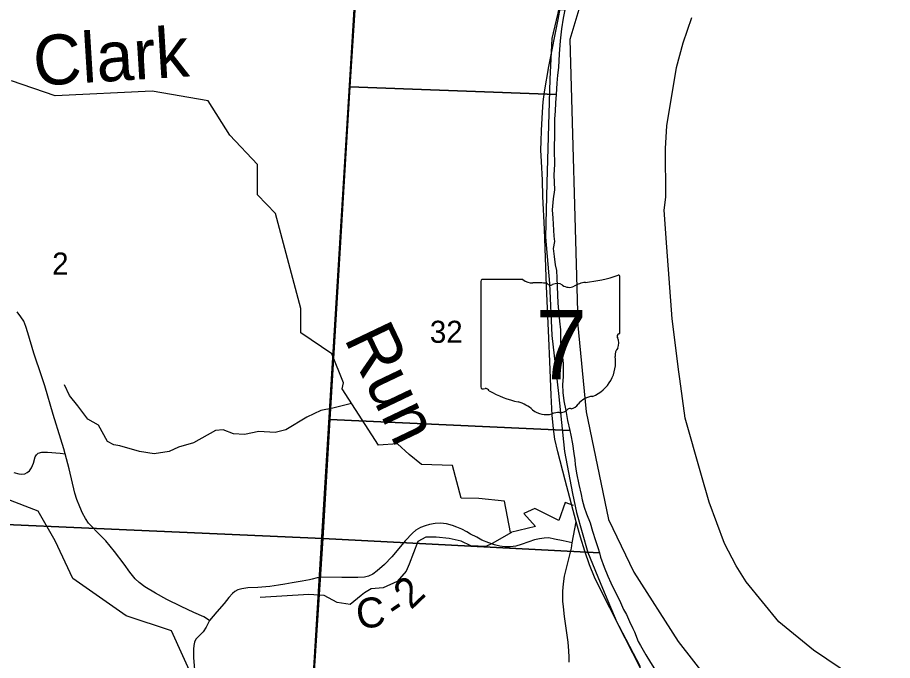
# Model space of a CAD drawing. Extents: x 1878108 to 2183446, y 146837 to 508383.
# Drawn here: x 2042273 to 2051033, y 280407 to 286848 of the extents above; entities that cross this region are included whole.
import ezdxf

# ---------------------------------------------------------------- set-up
doc = ezdxf.new("R2010")
doc.units = 0
for name, color, linetype in [('GM_X_County', 7, 'Continuous'), ('GM_X_County_Road', 7, 'Continuous'), ('GM_X_County_Road_Text', 7, 'Continuous'), ('GM_X_Major_River', 7, 'Continuous'), ('GM_X_Minor_River', 7, 'Continuous'), ('GM_X_Minor_River_Text', 7, 'Continuous'), ('GM_X_Section', 7, 'Continuous'), ('GM_X_Section_Text', 7, 'Continuous'), ('GM_X_State_Location', 7, 'Continuous'), ('GM_X_State_Route', 7, 'Continuous'), ('GM_X_State_Shield', 7, 'Continuous'), ('GM_X_Township', 7, 'Continuous'), ('GM_X_Township_Road', 7, 'Continuous')]:
    doc.layers.add(name, color=color, linetype=linetype)

msp = doc.modelspace()

# ---------------------------------------------------------------- linework, layer by layer
at = {"layer": 'GM_X_County'}
msp.add_lwpolyline([(2047973.9, 287198), (2047804.2, 286626.9), (2047880.1, 283903.6), (2047878.1, 283797.4), (2047965.9, 282897.6), (2048191.4, 281819.5), (2048444.9, 281292.4), (2048888.4, 280598.3), (2049170.8, 280234.4)], dxfattribs=at)
at = {"layer": 'GM_X_County_Road'}
for points in [[(2045221.5, 281222.3), (2045197.8, 281216.5), (2045124.2, 281200.7), (2045022.2, 281183.9), (2044948.6, 281172.3), (2044885.5, 281161.8), (2044800.3, 281149.2), (2044678.3, 281138.6), (2044580.4, 281134.4), (2044517.3, 281126), (2044479.5, 281115.5), (2044450, 281099.7), (2044424.8, 281078.7), (2044390.1, 281039.8), (2044341.7, 280978.8), (2044269.1, 280894.6), (2044230.2, 280850.5), (2044195.5, 280807.3), (2044136.6, 280845.2), (2044037.7, 280889.4), (2043910.5, 280949.3), (2043767.4, 281019.1), (2043654.9, 281081.8), (2043548.2, 281145.5), (2043489.8, 281188.1), (2043449.8, 281227), (2043397.2, 281293.2), (2043339.4, 281372.1), (2043244.7, 281499.4), (2043157.4, 281607.7), (2043064.9, 281700.3), (2043025.9, 281738.1), (2042982.2, 281784), (2042952.3, 281829.6), (2042923.9, 281882.2), (2042896.6, 281945.3), (2042868.2, 282019), (2042846.1, 282085.2), (2042790.4, 282327.1), (2042751.4, 282478.6), (2042736.7, 282529.1), (2042706.2, 282625.8), (2042628.4, 282873), (2042546.3, 283160.1), (2042516.9, 283247.4), (2042435.9, 283486.2), (2042374.9, 283689.2), (2042357, 283754.4), (2042334.9, 283804.9), (2042307.6, 283850.1), (2042269.7, 283898.5)], [(2047825.9, 281585.2), (2047734.7, 281606.7), (2047649, 281624), (2047591.6, 281635.1), (2047546.4, 281634), (2047498, 281626.7), (2047449.6, 281615.1), (2047391.8, 281595.1), (2047317.1, 281568.8), (2047262.4, 281553), (2047208.8, 281545.7), (2047152, 281546.7), (2047100.5, 281552), (2047050, 281566.7), (2046991.1, 281584.6), (2046922.7, 281614), (2046871.2, 281642.4), (2046808.7, 281672.4), (2046772.3, 281695), (2046721.8, 281721.3), (2046672.4, 281742.3), (2046629.3, 281761.3), (2046567.2, 281776), (2046508.3, 281783.4), (2046454.7, 281780.2), (2046398.9, 281768.6), (2046355.8, 281757.1), (2046307.4, 281738.1), (2046262.2, 281714), (2046226.5, 281681.3), (2046154.9, 281606.7), (2046073.9, 281509.9), (2046019.3, 281446.8), (2045945.6, 281370), (2045875.2, 281305.9), (2045831, 281271.2), (2045786.8, 281253.3), (2045745.8, 281242.8), (2045681.6, 281239.6), (2045518.6, 281239.6), (2045314.6, 281240.7), (2045294, 281238), (2045274.6, 281235.4), (2045221.5, 281222.3)], [(2044195.5, 280807.3), (2044162.8, 280740.2), (2044131.3, 280693.4), (2044059, 280622.6), (2044043.4, 280590.2), (2044037.6, 280558.7), (2044034.8, 280519.5), (2044034.8, 280433.5), (2044054.8, 280196.6)]]:
    msp.add_lwpolyline(points, dxfattribs=at)
at = {"layer": 'GM_X_Major_River'}
for points in [[(2047757, 287204.5), (2047623.5, 286636.6), (2047601.2, 286229.6), (2047573.4, 285191.2), (2047559.6, 284647.9), (2047599.4, 284183), (2047623.5, 283664), (2047687.7, 283082.9), (2047749.9, 282499.9), (2047829.4, 282081.3), (2047868.1, 281889), (2047981.5, 281490.6), (2048130.6, 281130.4), (2048273.7, 280790.2), (2048511.1, 280326.1)], [(2048763.6, 285047.7), (2048761.7, 285534.8), (2048774.7, 285763.3), (2048872.2, 286349), (2048939.1, 286593.9), (2049023.9, 286848.8)], [(2051033.4, 279977.5), (2050240.9, 280509.5), (2049894.4, 280794.7), (2049567.5, 281194.3), (2049469, 281354.3), (2049352.4, 281580.3), (2049199, 281992.6), (2049116, 282284.9), (2048956.1, 282835.5), (2048902.7, 283228.2), (2048894.4, 283298.3), (2048828.4, 283829.2), (2048773.6, 284548.6), (2048748.2, 284917.3), (2048763.6, 285047.7)]]:
    msp.add_lwpolyline(points, dxfattribs=at)
at = {"layer": 'GM_X_Minor_River'}
for points in [[(2047840.4, 281959.9), (2047756.9, 281991.4), (2047693.1, 281810.5), (2047451, 281930.6), (2047341.4, 281879.5), (2047459.4, 281750.3), (2047209.7, 281687.9), (2047149.4, 282004), (2046890.5, 282029.8), (2046714.1, 282032.2), (2046629.5, 282362.1), (2046316.8, 282369.4), (2046193.1, 282472.5), (2046077.5, 282577.7), (2045887.2, 282566), (2045523.1, 283127.9), (2045536.3, 283188.1), (2045420.2, 283479.7), (2045110.8, 283689.4), (2045109.6, 283933.9), (2044854.5, 284885.5), (2044675.7, 285072.3), (2044675.7, 285375), (2044397.2, 285671.1), (2044180.2, 286013.9), (2043621.7, 286109.1), (2042650.2, 286062.3), (2042213.3, 286212.8)], [(2045616.7, 282983.3), (2045431.1, 282934.2), (2045311, 282912), (2045168.9, 282845.6), (2044960.7, 282718.9), (2044852.6, 282690.6), (2044690.5, 282702.5), (2044546.4, 282670.3), (2044434.3, 282678.2), (2044330.2, 282718.2), (2044254.1, 282712.1), (2044033.9, 282589.4), (2043885.8, 282545.1), (2043789.7, 282500.8), (2043641.6, 282478.6), (2043493.5, 282500.5), (2043297.4, 282558.5), (2043237.3, 282568.5), (2043173.3, 282600.6), (2043083.3, 282763.1), (2042977.2, 282825.2), (2042875.2, 282957.6), (2042793.2, 283061.9), (2042743.2, 283168.3)], [(2044058.6, 280166.7), (2043815, 280705.6), (2043360, 280855.9), (2042826, 281229.9), (2042650.6, 281607.1), (2042478.4, 281902.2), (2041835.7, 282151)], [(2047219, 281690.2), (2047025.9, 281580.7), (2046961.8, 281550.5), (2046811.7, 281556.4), (2046715.6, 281602.5), (2046595.5, 281628.4), (2046465.4, 281644.4), (2046359.4, 281642.2), (2046281.3, 281600), (2046195.1, 281371.1), (2046163.1, 281300.8), (2046075, 281200.3), (2045934.9, 281135.9), (2045812.8, 281123.7), (2045746.7, 281085.5), (2045712.7, 281057.4), (2045602.5, 280966.9), (2045472.4, 280988.9), (2045342.4, 281057), (2045188.3, 281066.9), (2044703.9, 281038.3)]]:
    msp.add_lwpolyline(points, dxfattribs=at)
at = {"layer": 'GM_X_Section'}
for points in [[(2040106.5, 287265.7), (2045656.8, 287027), (2045601, 286154.5), (2045400.1, 282821.2), (2045329.4, 281630.4), (2039736.5, 281877.8)], [(2047752, 286926.7), (2047736, 286840.1), (2047718.4, 286734), (2047704.8, 286616), (2047695.2, 286483.9), (2047687.7, 286347.8), (2047678, 286269.8), (2047672.2, 286191.7), (2047666.9, 286077.2), (2045601, 286154.5), (2045656.8, 287027)], [(2045601, 286154.5), (2047666.9, 286077.2), (2047658.9, 285993.6), (2047657.2, 285909.6), (2047649.5, 285831.6), (2047648, 285693.5), (2047646.6, 285523.5), (2047649.1, 285375.5), (2047641.4, 285273.4), (2047649.9, 285123.4), (2047636.2, 285031.3), (2047626.6, 284923.2), (2047630.9, 284837.2), (2047641.5, 284657.2), (2047649.7, 284605.3), (2047636, 284535.2), (2047644.3, 284453.2), (2047656.6, 284369.2), (2047670.8, 284313.2), (2047671, 284241.2), (2047679.6, 284071.2), (2047683.9, 283985.2), (2047698.5, 283807.2), (2047710.8, 283719.2), (2047709.3, 283593.2), (2047725.7, 283471.2), (2047736, 283383.2), (2047736.4, 283249.2), (2047728.7, 283173.2), (2047733, 283093.1), (2047743.3, 283007.2), (2047761.6, 282911.2), (2047780, 282811.2), (2047801.9, 282712.8), (2045400.1, 282821.2)], [(2047801.9, 282712.8), (2047812.5, 282665.3), (2047828.8, 282579.3), (2047843.1, 282481.4), (2047853.4, 282417.4), (2047855.5, 282369.4), (2047867.9, 282283.4), (2047892.2, 282169.4), (2047916.6, 282069.5), (2047924.8, 282015.5), (2047947, 281943.6), (2047969.3, 281877.7), (2048007.6, 281785.8), (2048029.9, 281701.8), (2048060.2, 281607.9), (2048084.5, 281538), (2048098.3, 281484.7), (2045329.4, 281630.4), (2045400.1, 282821.2)], [(2045329.4, 281630.4), (2045240.9, 280250.1), (2044999.7, 276331.9), (2039465.5, 276603.9), (2039401.5, 276605.8), (2039736.5, 281877.8)], [(2048098.3, 281484.7), (2048108.8, 281444), (2048147.2, 281342.1), (2048183.5, 281252.2), (2048213.8, 281186.3), (2048233.9, 281142.4), (2048300.4, 281010.6), (2048340.7, 280918.7), (2048368.9, 280868.8), (2048401.1, 280796.9), (2048433.4, 280729), (2048451.5, 280695), (2048487.8, 280597.1), (2048510, 280557.2), (2048564.3, 280465.3), (2048610.6, 280387.5), (2048650.8, 280323.6), (2048695, 280267.7), (2048763.3, 280200), (2048873.7, 280088.3), (2048907.9, 280050.4), (2048930.5, 280024.5), (2045240.9, 280250.1), (2045329.4, 281630.4)]]:
    msp.add_lwpolyline(points, close=True, dxfattribs=at)
at = {"layer": 'GM_X_State_Route'}
for points in [[(2047865.5, 281796.9), (2047865.5, 281796.9), (2047755.7, 282214.1), (2047683.2, 282496.9), (2047654, 282623.1), (2047637.6, 282727.1), (2047627.1, 282863.8), (2047615.4, 283066), (2047602.6, 283403.8), (2047592.7, 283637.4), (2047569.8, 284158.7), (2047547.6, 284726.7), (2047532.4, 285055), (2047527.8, 285217.5), (2047518.4, 285405.6), (2047513.7, 285519), (2047514.9, 285609), (2047517.7, 285714.8), (2047527.8, 285900), (2047537.1, 286005.1), (2047547.6, 286104.5), (2047590.9, 286356.9), (2047684.4, 286826.7), (2047729.9, 287070.9)], [(2047839.1, 281655.8), (2047865.5, 281796.9)], [(2048510.9, 280344.4), (2048296.4, 280751.7), (2048112.3, 281112.3), (2048051.3, 281242.8), (2048000.8, 281366.9), (2047952.4, 281501.5), (2047908.2, 281641.4), (2047865.5, 281796.9)], [(2047796.7, 280390.8), (2047796.7, 280442.4), (2047793.6, 280504.4), (2047785.2, 280591.7), (2047773.6, 280684.3), (2047750.5, 280847.3), (2047738.9, 280944.1), (2047733.6, 281001.9), (2047732.6, 281052.4), (2047732.6, 281102.9), (2047737.8, 281176.5), (2047750.5, 281251.2), (2047769.4, 281333.2), (2047817.8, 281533), (2047825.9, 281585.2), (2047839.1, 281655.8)]]:
    msp.add_lwpolyline(points, dxfattribs=at)
at = {"layer": 'GM_X_State_Shield'}
for p, q in [((2046912.2, 284204.8), (2046912.2, 283148.2)), ((2047333.6, 284223), (2046925.9, 284223)), ((2048304.3, 283696.4), (2048304.3, 284249.2)), ((2048304.2, 283696.6), (2048304.3, 283696.4))]:
    msp.add_line(p, q, dxfattribs=at)
for centre, radius, start, end in [((2046928.1, 284207.1), 16.1, 98.1301, 188.1301), ((2047430.7, 284345.7), 156.4, 231.61951, 271.11188), ((2047808.4, 285663.6), 1476.4, 275.84447, 288.90645), ((2048288.9, 284251.5), 15.5, 351.86209, 97.738), ((2047482.5, 283629.8), 561.6, 80.48669, 94.98827), ((2047610, 284212.5), 45.1, 219.79206, 297.10237), ((2047676.3, 284090.4), 93.8, 54.46668, 119.14113), ((2047797.4, 284257.9), 112.9, 233.85621, 294.82819), ((2047996.7, 283900.3), 297, 97.34618, 120.76885), ((2048300.7, 283655.9), 24, 107.94398, 210.33697), ((2048287.8, 283694.3), 16.6, 289.60381, 7.73413), ((2048148.2, 283586), 144, 340.03296, 23.64957), ((2048359.9, 283465.1), 104.8, 136.8065, 186.92959), ((2047891.1, 283394.8), 369.3, 292.30889, 8.98584), ((2046928.3, 283145.9), 16.3, 171.95839, 258.30661), ((2046930.7, 283254), 124.2, 267.33899, 280.60386), ((2046956.1, 283087.2), 44.8, 29.74838, 93.27175), ((2047521.4, 284036.6), 1066.1, 240.41292, 257.1985), ((2047203.6, 282673.5), 333.6, 47.18416, 75.83597), ((2048046.8, 282851.5), 202.2, 94.40312, 142.57675), ((2047564.3, 283082), 211.7, 230.70037, 286.29184), ((2047686.6, 282716.7), 173.9, 85.69512, 111.20995), ((2047702.1, 283002.9), 112.8, 268.77702, 315.54927), ((2047804.1, 282900.5), 31.8, 65.75173, 132.64842), ((2047790.6, 283045.8), 119.3, 282.87319, 323.27711)]:
    msp.add_arc(centre, radius, start, end, dxfattribs=at)
at = {"layer": 'GM_X_Township'}
for points in [[(2041416.6, 309015.4), (2043687.2, 308920.5), (2044671.3, 308870.3), (2046896.4, 308713), (2046850.7, 307315.9), (2046837.6, 306990.7), (2046818.9, 306761.3), (2046274.1, 297148.3), (2046004.2, 292592), (2045984.8, 292287.1), (2045909.9, 291035.1), (2045645.1, 286985.8), (2045292.2, 281208.8), (2045231.9, 280221.7), (2044993.2, 276329), (2043134.5, 276417.7), (2042678.2, 276439.4), (2039443.8, 276593.8)], [(2047973.9, 287198), (2047804.2, 286626.9), (2047880.1, 283903.6), (2047878.1, 283797.4), (2047965.9, 282897.6), (2048191.4, 281819.5), (2048444.9, 281292.4), (2048888.4, 280598.3), (2049170.8, 280234.4), (2049415.2, 279995.5), (2048679.2, 280024.2), (2047735.6, 280098.7), (2045231.9, 280221.7), (2045292.2, 281208.8), (2045645.1, 286985.8)]]:
    msp.add_lwpolyline(points, dxfattribs=at)
at = {"layer": 'GM_X_Township_Road'}
msp.add_lwpolyline([(2042235, 282291.4), (2042286.6, 282276.6), (2042317.1, 282272.4), (2042345.5, 282277.7), (2042369.6, 282290.3), (2042393.8, 282307.1), (2042413.8, 282337.6), (2042432.8, 282382.9), (2042448.5, 282446), (2042463.3, 282468.1), (2042478, 282483.8), (2042515.8, 282493.3), (2042571.6, 282493.3), (2042698.8, 282482.8), (2042751.4, 282478.6)], dxfattribs=at)

# ---------------------------------------------------------------- texts
at = {"layer": 'GM_X_County_Road_Text'}
for s, rotation, p in [('2', 43.84605, (2046213.4, 280909)), ('C', 7.70399, (2045683.8, 280719.1)), ('-', 33.77526, (2046066.2, 280804.5))]:
    msp.add_text(s, height=300, rotation=rotation, dxfattribs=at).set_placement(p)
at = {"layer": 'GM_X_Minor_River_Text'}
for s, height, rotation, p in [('Clark', 500, 3.51112, (2042444.3, 286162.9)), ('Run', 500.03, 295.51234, (2045537.5, 283635.4))]:
    msp.add_text(s, height=height, rotation=rotation, dxfattribs=at).set_placement(p)
at = {"layer": 'GM_X_Section_Text'}
for s, p in [('2', (2042619.6, 284273.2)), ('32', (2046401.3, 283589.5))]:
    msp.add_text(s, height=221, rotation=0.00001, dxfattribs=at).set_placement(p)
at = {"layer": 'GM_X_State_Location'}
for s in ['s', 'r']:
    msp.add_text(s, height=1, dxfattribs=at).set_placement((2047592.5, 283606.3))
msp.add_text('7', height=1, rotation=0.00001, dxfattribs=at).set_placement((2047441.9, 283533.5))
at = {"layer": 'GM_X_State_Shield'}
msp.add_text('7', height=696.1, dxfattribs=at).set_placement((2047458.1, 283222.7))

doc.saveas('drawing.dxf')
